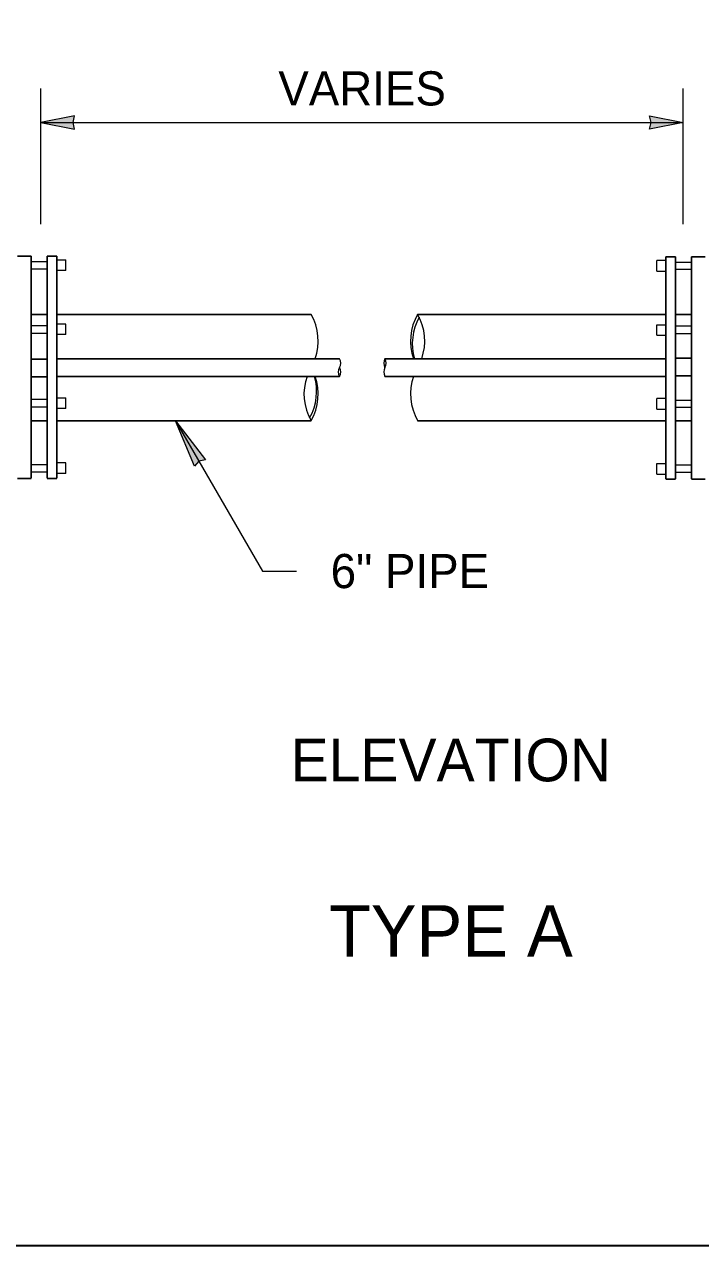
# Model space of a CAD drawing. Extents: x 99860 to 103153, y 99998 to 102077.
# Drawn here: x 100475 to 100792, y 100000 to 100571 of the extents above; entities that cross this region are included whole.
import ezdxf
from ezdxf.enums import TextEntityAlignment as Align

# ---------------------------------------------------------------- set-up
doc = ezdxf.new("R2010")
doc.units = 0
doc.header["$LTSCALE"] = 6.4
for name, color, linetype, lineweight in [('1', 7, 'Continuous', 25), ('15', 7, 'Continuous', 13), ('18', 7, 'Continuous', 13), ('20', 7, 'Continuous', 13), ('6', 7, 'Continuous', 25)]:
    doc.layers.add(name, color=color, linetype=linetype, lineweight=lineweight)

msp = doc.modelspace()

# ---------------------------------------------------------------- hatches: boundary and pattern name
at = {"layer": '15'}
for points in [[(100483.007, 100525.21), (100498.732, 100522.126), (100498.004, 100525.21), (100498.732, 100528.294)], [(100783.782, 100525.21), (100768.057, 100522.126), (100768.785, 100525.21), (100768.057, 100528.294)], [(100546.056, 100385.623), (100560.055, 100367.345), (100556.941, 100366.769), (100554.885, 100364.36)]]:
    msp.add_hatch(color=256, dxfattribs=at).paths.add_polyline_path(points)

# ---------------------------------------------------------------- linework, layer by layer
at = {"layer": '1', "lineweight": 35}
msp.add_lwpolyline([(99862, 99999.5), (103151, 99999.5), (103151, 102075.5), (99862, 102075.5)], close=True, dxfattribs=at)
at = {"layer": '15'}
for p, q in [((100483.007, 100477.71), (100483.007, 100541.21)), ((100783.782, 100477.71), (100783.782, 100541.21)), ((100483.007, 100525.21), (100783.782, 100525.21)), ((100546.056, 100385.623), (100586.681, 100315.258)), ((100586.681, 100315.258), (100602.681, 100315.258))]:
    msp.add_line(p, q, dxfattribs=at)
for points in [[(100483.007, 100525.21), (100498.732, 100522.126), (100498.004, 100525.21), (100498.732, 100528.294)], [(100783.782, 100525.21), (100768.057, 100522.126), (100768.785, 100525.21), (100768.057, 100528.294)], [(100546.056, 100385.623), (100560.055, 100367.345), (100556.941, 100366.769), (100554.885, 100364.36)]]:
    msp.add_lwpolyline(points, close=True, dxfattribs=at)
at = {"layer": '18', "lineweight": 25}
for p, q in [((100472.057, 100462.71), (100478.432, 100462.71)), ((100478.432, 100358.76), (100478.432, 100462.71)), ((100485.895, 100462.71), (100485.895, 100358.76)), ((100485.895, 100462.71), (100490.407, 100462.71)), ((100490.407, 100358.76), (100490.407, 100462.71)), ((100775.67, 100358.46), (100775.67, 100462.397)), ((100780.17, 100462.397), (100775.67, 100462.397)), ((100780.17, 100462.397), (100780.17, 100358.46)), ((100787.632, 100358.46), (100787.632, 100462.397)), ((100794.02, 100462.397), (100787.632, 100462.397)), ((100478.432, 100414.422), (100485.895, 100414.422)), ((100490.407, 100414.635), (100622.806, 100414.635)), ((100644.081, 100414.635), (100775.545, 100414.635)), ((100787.632, 100414.885), (100780.207, 100414.885)), ((100478.432, 100406.185), (100485.895, 100406.185)), ((100490.407, 100406.41), (100622.806, 100406.41)), ((100644.081, 100406.41), (100775.545, 100406.41)), ((100787.632, 100406.647), (100780.207, 100406.647)), ((100472.057, 100358.61), (100478.432, 100358.61)), ((100485.895, 100358.61), (100490.407, 100358.61)), ((100780.17, 100358.297), (100775.67, 100358.297)), ((100794.02, 100358.297), (100787.632, 100358.297))]:
    msp.add_line(p, q, dxfattribs=at)
at = {"layer": '18'}
for p, q in [((100478.432, 100460.16), (100485.895, 100460.16)), ((100478.432, 100456.672), (100485.895, 100456.672)), ((100490.407, 100460.897), (100494.657, 100460.897)), ((100494.657, 100455.922), (100494.657, 100460.897)), ((100775.52, 100460.585), (100771.407, 100460.585)), ((100771.407, 100455.622), (100771.407, 100460.585)), ((100780.17, 100459.872), (100787.632, 100459.872)), ((100787.632, 100456.36), (100780.17, 100456.36)), ((100494.657, 100455.922), (100490.407, 100455.922)), ((100771.407, 100455.622), (100775.52, 100455.622)), ((100478.432, 100430.185), (100485.895, 100430.185)), ((100494.657, 100430.885), (100490.557, 100430.885)), ((100494.657, 100425.922), (100494.657, 100430.885)), ((100771.407, 100430.585), (100775.52, 100430.585)), ((100771.407, 100425.61), (100771.407, 100430.585)), ((100787.632, 100429.872), (100780.17, 100429.872)), ((100478.432, 100426.697), (100485.895, 100426.697)), ((100494.657, 100425.922), (100490.557, 100425.922)), ((100771.407, 100425.61), (100775.52, 100425.61)), ((100787.632, 100426.385), (100780.17, 100426.385)), ((100485.895, 100395.647), (100478.432, 100395.647)), ((100490.407, 100396.347), (100494.695, 100396.347)), ((100494.695, 100391.385), (100494.695, 100396.347)), ((100775.67, 100396.047), (100771.382, 100396.047)), ((100771.382, 100391.072), (100771.382, 100396.047)), ((100780.17, 100395.335), (100787.632, 100395.335)), ((100478.432, 100392.122), (100485.895, 100392.122)), ((100494.695, 100391.385), (100490.407, 100391.385)), ((100771.382, 100391.072), (100775.67, 100391.072)), ((100787.632, 100391.822), (100780.17, 100391.822)), ((100478.432, 100365.11), (100485.895, 100365.11)), ((100494.695, 100365.86), (100490.407, 100365.86)), ((100494.695, 100360.885), (100494.695, 100365.86)), ((100771.382, 100365.547), (100775.67, 100365.547)), ((100771.382, 100360.585), (100771.382, 100365.547)), ((100478.432, 100361.66), (100485.895, 100361.66)), ((100494.695, 100360.885), (100490.407, 100360.885)), ((100771.382, 100360.585), (100775.67, 100360.585)), ((100787.632, 100364.81), (100780.17, 100364.81)), ((100787.632, 100361.347), (100780.17, 100361.347))]:
    msp.add_line(p, q, dxfattribs=at)
for centre, start, end in [((100619.245, 100412.578), 330, 30), ((100647.643, 100412.578), 150, 210), ((100640.52, 100412.578), 330, 30), ((100626.368, 100408.466), 150, 210), ((100619.245, 100408.466), 330, 30), ((100647.643, 100408.466), 150, 210)]:
    msp.add_arc(centre, 4.112, start, end, dxfattribs=at)
at = {"layer": '6'}
for p, q in [((100478.432, 100435.385), (100485.895, 100435.385)), ((100490.407, 100435.385), (100609.504, 100435.385)), ((100659.4, 100435.385), (100775.52, 100435.385)), ((100780.17, 100435.385), (100787.632, 100435.385)), ((100478.432, 100385.622), (100485.895, 100385.622)), ((100490.407, 100385.622), (100609.504, 100385.622)), ((100659.4, 100385.622), (100775.67, 100385.622)), ((100780.17, 100385.622), (100787.632, 100385.622))]:
    msp.add_line(p, q, dxfattribs=at)
at = {"layer": '6', "lineweight": 13}
for centre, radius, start, end in [((100587.984, 100422.96), 24.85, 340.42686, 30), ((100680.921, 100422.96), 24.85, 150, 199.57314), ((100682.74, 100421.621), 25.837, 151.17581, 195.68784), ((100637.88, 100422.96), 24.85, 340.42686, 30), ((100631.025, 100398.11), 24.85, 160.488, 210), ((100587.451, 100399.33), 24.659, 329.97677, 16.68449), ((100587.984, 100398.11), 24.85, 330, 19.512), ((100680.921, 100398.11), 24.85, 160.488, 210)]:
    msp.add_arc(centre, radius, start, end, dxfattribs=at)

# ---------------------------------------------------------------- texts
at = {"layer": '20'}
for s, height, p in [('VARIES', 16, (100633.397, 100533.21)), ('ELEVATION', 20, (100674.947, 100216.818)), ('TYPE A', 24, (100674.948, 100134.818))]:
    msp.add_text(s, height=height, dxfattribs=at).set_placement(p, align=Align.CENTER)
msp.add_text('6" PIPE', height=16, dxfattribs=at).set_placement((100618.681, 100307.258))

doc.saveas('drawing.dxf')
